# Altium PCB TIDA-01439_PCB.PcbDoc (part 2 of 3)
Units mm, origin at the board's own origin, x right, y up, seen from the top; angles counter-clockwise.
Board outline 105.8 x 40.5 mm, 4 copper layers (Layer 1 - Top Layer, Layer 2 - GND, Layer 3 - POWER, Layer 4 - Bottom Layer), stack 1.56 mm thick; 145 components, 123 nets, 523 pads, 227 vias.
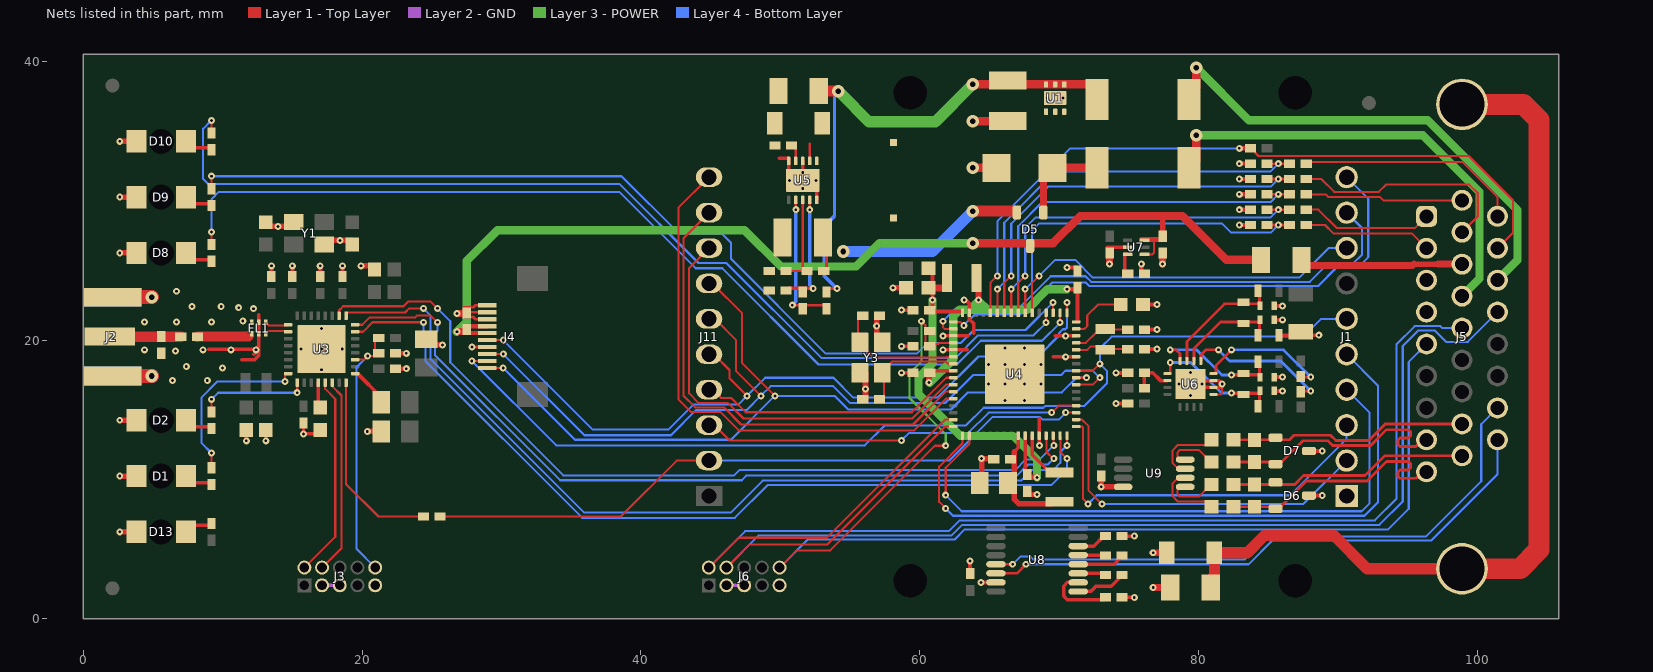
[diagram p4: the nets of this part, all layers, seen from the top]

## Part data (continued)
R10: "RES, 91.0 k, 0.1%, 0.1 W, 0603", Manufacturer="Susumu Co Ltd", Power_W=0.1, Supplier Part Number 1=RG16P91.0KBCT-ND, TempCo="25 ppm/C", Value1=0.1%, Value2=0.1W, Value_Code=91k0, ValueDisplayed=91.0k
R11: "RES, 10.0 k, 1%, 0.063 W, 0402", Manufacturer=Vishay-Dale, Power_W=0.063, Supplier Part Number 1=541-10.0KLCT-ND, TempCo="100 ppm/C", Tolerance_%=1, Value1=1%, Value2=0.063W, Value_Code=10k0, ValueDisplayed=10.0k
R13 R16 R21 R23 R25: "RES, 18.0 k, 1%, 0.063 W, AEC-Q200 Grade 0, 0402", Manufacturer=Vishay-Dale, Power_W=0.063, Supplier Part Number 1=541-18.0KLCT-ND, TempCo="100 ppm/C", Tolerance_%=1, Value1=1%, Value2=0.063W, Value_Code=18k0, ValueDisplayed=18.0k
R14 R19 R22 R24 R26: "RES, 33 k, 5%, 0.063 W, 0402", Manufacturer=Vishay-Dale, Power_W=0.063, Supplier Part Number 1=541-33KJCT-ND, TempCo="200 ppm/C", Tolerance_%=5, Value1=5%, Value2=0.063W, Value_Code=33k0, ValueDisplayed=33k
R15: "RES, 2.00 M, 1%, 0.063 W, 0402", Manufacturer=Vishay-Dale, Power_W=0.063, Supplier Part Number 1=541-2.00MLCT-ND, TempCo="100 ppm/C", Tolerance_%=1, Value1=1%, Value2=0.063W, Value_Code=2M00, ValueDisplayed=2.00M
R17: "RES, 130 k, 5%, 0.063 W, 0402", Manufacturer=Vishay-Dale, Power_W=0.063, Supplier Part Number 1=541-130KJCT-ND, TempCo="200 ppm/C", Tolerance_%=5, Value1=5%, Value2=0.063W, Value_Code=130k
R18: "RES, 110 k, 1%, 0.063 W, 0402", Manufacturer=Vishay-Dale, Power_W=0.063, Supplier Part Number 1=541-110KLCT-ND, TempCo="100 ppm/C", Tolerance_%=1, Value1=1%, Value2=0.063W, Value_Code=110k
R20: "RES, 24.9 k, 1%, 0.063 W, 0402", Manufacturer=Vishay-Dale, Power_W=0.063, Supplier Part Number 1=541-24.9KLCT-ND, TempCo="100 ppm/C", Tolerance_%=1, Value1=1%, Value2=0.063W, Value_Code=24k9, ValueDisplayed=24.9k
R27 R29 R30 R31: "RES, 4.12k ohm, 0.1%, 0.1W, 0603", Manufacturer="Susumu Co Ltd", Power_W=0.1, Supplier Part Number 1=RG16P4.12KBCT-ND, TempCo="25 ppm/C", Value1=0.1%, Value2=0.1W, Value_Code=4k12
R28: "RES, 3.24k ohm, 0.1%, 0.333W, 1206", Manufacturer="TT Electronics/IRC", Power_W=0.333, Supplier Part Number 1=66-PFC12L3.24K-B, TempCo="10 ppm/C", Tolerance_%=0.1, Value1=0.1%, Value2=0.333W, Value_Code=3k24
R32: "RES, 383 k, 1%, 0.063 W, 0402", Manufacturer=Vishay-Dale, Power_W=0.063, Supplier Part Number 1=541-383KLCT-ND, TempCo="100 ppm/C", Tolerance_%=1, Value1=1%, Value2=0.063W, Value_Code=383k
R34 R35 R36 R37: "RES, 10, 5%, 0.25 W, 0603", Manufacturer=Vishay-Dale, Power_W=0.25, Supplier Part Number 1=541-10SACT-ND, TempCo="200 ppm/C", Tolerance_%=5, Value1=5%, Value2=0.25W, Value_Code=10R0, ValueDisplayed=10
R41 R42: "RES, 120, 5%, 0.1 W, 0603", Manufacturer=Vishay-Dale, Power_W=0.1, Supplier Part Number 1=541-120GCT-ND, TempCo="200 ppm/C", Tolerance_%=5, Value1=5%, Value2=0.1W, Value_Code=120R, ValueDisplayed=120
R43 R44: "RES, 100, 5%, 0.25 W, 1206", Manufacturer=Vishay-Dale, Power_W=0.25, Supplier Part Number 1=541-100ECT-ND, TempCo="200 ppm/C", Tolerance_%=5, Value1=5%, Value2=0.25W, Value_Code=100R, ValueDisplayed=100
U1: "33V Precision Surge Protection Clamp, DRV0006A (WSON-6)", Alternate Manufacturer="Texas Instruments", Alternate PartNumber=TVS3300DRVT
U3: "Ultra low-power ARM Cortex M3 2.4 GHz Radio MCU, Multi-Protocol, RSHB032E", Alternate Manufacturer="Texas Instruments", Alternate PartNumber=CC2650F128RHBT
U4: "Low-Power and High Performance 32-Bit ARM Cortex M4F With 256KB Flash and 64KB RAM, RGC0064B (VQFN-64)", Alternate Manufacturer="Texas Instruments", Alternate PartNumber=MSP432P401RIRGCT
U5: "3V-65V, 150mA Synchronous Buck Converter With Ultra-Low IQ, DRC0010J (VSON-10)", Alternate Manufacturer="Texas Instruments", Alternate PartNumber=LM5165DRCT
U6: "24-Bit, 2kSPS, 4-Ch, Low-Power, Delta-Sigma ADC with PGA  and Voltage Reference, RVA0016A (VQFN-16)", Alternate Manufacturer="Texas Instruments", Alternate PartNumber=ADS1220IRVAT
U7: "Single Output High PSRR LDO, 150 mA, Fixed 3.3 V Output, 2.5 to 6.5 V Input, with Low IQ, 6-pin WSON (DSE), -40 to 125 degC, Green (RoHS & no Sb/Br)", Alternate Manufacturer="Texas Instruments", Alternate PartNumber=Equivalent, Supplier Part Number 1=296-22054-2-ND
U8: "3-V to 5.5-V Multichannel RS-232 Line Driver / Receiver with ±15-kV IEC ESD Protection, -40 to 85 degC, 16-Pin TSSOP (PW), Green (RoHS & no Sb/Br)", Alternate Manufacturer="Texas Instruments", Alternate PartNumber=Equivalent, Drivers Per Package=2, Supplier Part Number 1=296-19436-2-ND, Supply Voltage(s)(V)="3.3 or 5.0"
U9: "3.3-V Full-Duplex RS-485 Transceivers With 12-kV IEC ESD, DGK0008A (VSSOP-8)", Alternate Manufacturer="Texas Instruments", Alternate PartNumber=SN65HVD71DGK
Y1: "Crystal, 24 MHz, 9 pF, SMD", Frequency="24 MHz", Frequency Stability=±20ppm, Manufacturer=Epson, Supplier Part Number 1=SER3634CT-ND
Y2 Y4: "Crystal, 32.768kHz, 12.5pF, SMD", Frequency=32.768KHZ, Frequency Stability=±20ppm, Manufacturer=Epson, Supplier Part Number 1=SER3672CT-ND
Y3: "Crystal, 48MHz, 12pF, SMD", Frequency=48MHz, Frequency Stability=±30ppm, Manufacturer=Epson, Supplier Part Number 1="FA-238 48.0000MB-W0-ND"
ZZ1: library part AssemblyNoteLabel, Alternate Manufacturer=-
ZZ2 ZZ3 ZZ4: library part AssemblyNote, Alternate Manufacturer=-

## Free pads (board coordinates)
  round 0.1 hole 2.4 unplated paste-1 mask+0.1: ""(59.3,2.75) ""(59.3,37.75) ""(86.9,2.75) ""(86.9,37.75)

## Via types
v1: diameter 0.5, hole 0.2, Layer 1 - Top Layer to Layer 4 - Bottom Layer, 215 vias
v2: diameter 0.9, hole 0.4, Layer 1 - Top Layer to Layer 4 - Bottom Layer, 12 vias

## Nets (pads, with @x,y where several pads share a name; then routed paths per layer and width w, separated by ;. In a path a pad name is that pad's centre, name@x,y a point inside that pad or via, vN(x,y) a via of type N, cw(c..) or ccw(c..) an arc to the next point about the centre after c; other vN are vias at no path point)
5V: C6.1 C28.1 D5.3 J4.6 J4.7 R43.1 U7.4 U7.6 | length 81.5
  Layer 1 - Top Layer w0.15: U7.4@76.1,26.15 76.675,26.15 76.775,26.25 76.775,27.075
  Layer 1 - Top Layer w0.25: 75.875,27.275 77.575,27.275 77.575,27.15 U7.6@76.1,27.15
  Layer 1 - Top Layer w0.3: J4.6@28.974,20.496 27.5,20.496 C6.1@27.5,20.75 27.5,20.996 J4.7@28.974,20.996
  Layer 1 - Top Layer w0.4: C28.1@77.4,27.45 77.4,28.8
  Layer 1 - Top Layer w0.5: v1(26.8,20.6) C6.1@27.397,20.6
  Layer 1 - Top Layer w0.6: D5.3@67.9,26.9 67.85,26.95 v2(63.8,26.95) 69.55,26.95 71.5,28.9 78.825,28.9 81.975,25.75 R43.1@84.45,25.75
  Layer 3 - POWER w0.6: v1(26.8,20.6) 27.5,21.3 27.5,25.675 29.7,27.875 47.425,27.875 50.025,25.275 55.425,25.275 57.1,26.95 v2(63.8,26.95)
5V_IN: F1.2 J5.13 | length 31.8
  Layer 1 - Top Layer w0.6: F1.2@79.825,32.875 v2(79.825,34.675)
  Layer 3 - POWER w0.6: v2(79.825,34.675) 96.075,34.675 100.125,30.625 100.125,24.405 J5.13@98.87,23.15
5V_OUT: J5.12 R43.2 | length 12
  Layer 1 - Top Layer w0.4: 95.415,25.44 97.16,25.44
  Layer 1 - Top Layer w0.5: R43.2@87.35,25.333 95.308,25.333 95.415,25.44 ; 97.16,25.44 J5.12@98.87,25.44
  Layer 1 - Top Layer w0.6: R43.2@87.35,25.333 R43.2@87.35,25.75
24V_IN: F2.2 J5.21 | length 34.4
  Layer 1 - Top Layer w0.6: F2.2@79.825,38.05 v2(79.825,39.525)
  Layer 3 - POWER w0.6: v2(79.825,39.525) 83.6,35.75 96.425,35.75 102.85,29.325 102.85,25.735 J5.21@101.41,24.295
AIN0: C44.2 C45.2 R31.2 U6.9 | length 9.4
  Layer 1 - Top Layer w0.2: U6.9@77.75,17.6 77.95,17.6 v1(77.95,18.4)
  Layer 1 - Top Layer w0.25: v1(82.35,16.2) 84.35,16.2 84.35,15.25 R31.2@84.238,15.25
  Layer 4 - Bottom Layer w0.2: v1(77.95,18.4) 79.418,18.4 81.618,16.2 v1(82.35,16.2)
AIN1: C43.1 C44.1 R30.2 U6.8 | length 9.5
  Layer 1 - Top Layer w0.2: v1(77.95,19.3) 78.375,19.3 78.65,19.025 U6.8@78.65,18.5
  Layer 1 - Top Layer w0.25: v1(82.35,17.5) 84.35,17.5 84.35,18.45 R30.2@84.238,18.45
  Layer 4 - Bottom Layer w0.2: v1(77.95,19.3) 79.85,19.3 81.65,17.5 v1(82.35,17.5)
AIN2: D4.2 U6.5 | length 10.5
  Layer 1 - Top Layer w0.2: U6.5@80.15,18.5 80.15,18.95 80.5,19.3 v1(81.4,19.3) ; D4.2@87.3,16.3 87.3,16.35 v1(88.025,16.35)
  Layer 4 - Bottom Layer w0.2: v1(81.4,19.3) 82.2,18.5 85.875,18.5 v1(88.025,16.35)
AIN3: D3.2 U6.4 | length 9.6
  Layer 1 - Top Layer w0.2: U6.4@81.05,17.6 81.225,17.6 81.225,18.175 v1(82.35,19.3) ; D3.2@87.3,17.4 87.3,17.35 v1(88.025,17.35)
  Layer 4 - Bottom Layer w0.2: v1(82.35,19.3) 86.075,19.3 v1(88.025,17.35)
CC2650_CLK: U3.26 U4.14 | length 60.4
  Layer 1 - Top Layer w0.15: U3.26@18.35,21.75 18.35,22.125 18.65,22.425 22.975,22.425 23.325,22.775 24.9,22.775 v1(25.4,22.275) ; v1@69.575,12.45 U4.14@69.575,13.15
  Layer 4 - Bottom Layer w0.15: v1(25.4,22.275) 26.325,21.35 26.325,18.4 34.425,10.3 46.675,10.3 47.05,10.675 66.825,10.675 67.6,11.45 68.6,11.45 v1(69.6,12.45)
CC2650_NCS: U3.24 U4.13 | length 59.4
  Layer 1 - Top Layer w0.15: U3.24@19.5,21.1 20.025,21.1 20.55,21.625 23.825,21.625 23.975,21.775 24.9,21.775 v1(25.4,21.275) ; U4.13@69.025,13.175 U4.13@69.05,13.15 69.075,13.125 69.075,11.975 v1@69.55,11.5
  Layer 4 - Bottom Layer w0.15: v1(25.4,21.275) 25.4,20.65 25.225,20.475 25.225,18.925 34.2,9.95 47.225,9.95 47.55,10.275 66.95,10.275 67.75,11.075 69.175,11.075 v1(69.6,11.5)
CC2650_SIMO: U3.25 U4.16 | length 63.1
  Layer 1 - Top Layer w0.15: U3.25@18.85,21.75 18.85,21.975 23.075,21.975 23.375,22.275 v1(24.4,22.275) ; v1(70.55,12.45) U4.16@70.55,13.15
  Layer 4 - Bottom Layer w0.15: v1(24.4,22.275) 24.9,21.775 24.9,18.65 35.925,7.625 46.425,7.625 48.725,9.925 67.25,9.925 68,10.675 69.55,10.675 70.075,11.2 70.075,11.975 v1(70.55,12.45)
CC2650_SOMI: U3.23 U4.15 | length 62.8
  Layer 1 - Top Layer w0.15: U3.23@19.5,20.6 20.075,20.6 20.75,21.275 v1(24.4,21.275) ; U4.15@70.05,13.15 70.075,13.125 70.075,11.975 v1(70.55,11.5)
  Layer 4 - Bottom Layer w0.15: v1(24.4,21.275) 24.4,20.7 24.55,20.55 24.55,18.475 35.775,7.25 46.725,7.25 49.075,9.6 69.425,9.6 70.55,10.725 v1(70.55,11.5)
DCDC_SW: L2.1 U3.17 | length 2.6
  Layer 1 - Top Layer w0.25: U3.17@19.5,17.6 19.675,17.6 21.384,15.891 L2.1@21.384,15.85
GND: C1.2 C2.2 C3.2 C4.2 C5.2 C6.2 C7.2 C8.2 C9.2 C10.2 C11.2 C13.2 C14.2 C15.1 C16.2 C17.2 C18.2 C19.2 C20.2 C21.2 C22.2 C23.2 C24.2 C25.2 C26.2 C27.2 C28.2 C29.1 C30.2 C31.2 C32.2 C33.2 C34.2 C35.1 C36.2 C37.1 C38.2 C40.1 C41.2 C42.2 C43.2 C45.1 C48.2 C49.2 C50.2 C51.2 C52.2 C53.1 D1.2 D2.2 D6.3 D7.3 D8.2 D9.2 D10.2 D11.2 D13.2 FL1.2 FL1.5 FL1.6 J1.1 J2.2 J2.3 J2.4 J2.5 J3.3 J3.5 J3.9 J4.4 J4.8 J4.9 J4.10 J5.3 J5.4 J6.3 J6.5 J6.9 R10.1 R14.1 R18.1 R19.1 R20.1 R22.1 R24.1 R26.1 R28.1 R29.1 R44.1 U1.1 U1.2 U1.3 U1.7@69.7,37.35 U3.33 U4.12 U4.27 U4.30 U4.47 U4.51 U4.53 U4.65@66.8,17.55 U5.3 U5.5 U5.10 U5.11 U6.1 U6.2 U6.3 U6.17 U7.2 U8.15 U9.4 Y1.2 Y1.4 Y3.2 Y3.4 | length 119.9
  Layer 1 - Top Layer w0.15: U6.1@81.05,16.1 81.55,16.1 81.675,16.225 v1(81.675,16.85)
  Layer 1 - Top Layer w0.2: C6.2@27.3,22.35 28,22.35 28.146,22.497 J4.10@28.974,22.497 ; C6.2@27.35,21.65 27.975,21.65 28.129,21.497 J4.8@28.974,21.497 ; C6.2@27.428,21.996 27.5,21.996 J4.9@28.974,21.996 ; v1(27.879,19.496) J4.4@28.974,19.496
  Layer 1 - Top Layer w0.25: 8.996,19.325 12.354,19.325 12.575,19.546 ; 11.375,18.575 12.275,18.575 12.575,18.875 v1@12.575,19.3 ; FL1.6@12.079,21.2 FL1.6@12.079,21.278 ; 12.25,18.975 v1@12.575,19.3 ; 12.575,19.55 12.575,19.546 ; 12.579,21.8 FL1.5@12.579,21.278 FL1.2@12.579,20.453 12.579,19.55 12.575,19.546 ; C3.2@15.8,14.1 v1(15.8,13.275) 17.2,13.275 C13.2@17.2,13.6 ; C18.2@19.1,26.85 19.1,27.15 C18.2@19.1,27.225 ; 49.9,33.025 50.6,33.025 U5.5@50.6,32.85 U5.11@50.6,31.8 ; U5.11@51.6,31.525 v1(51.6,32.025) U5.3@51.6,32.85 ; U5.10@52.6,30.05 U5.11@52.6,30.975 ; v1(58.675,17.65) C22.2@59.5,17.65 ; v1(58.675,19.55) C34.2@59.5,19.55 ; v1(58.675,22.15) C25.2@59.5,22.15 ; v1(61.65,19.3) 62.4,19.3 63.4,19.3 ; v1(61.65,20.3) U4.51@62.401,20.3 ; U4.51@62.4,20.301 63.449,20.301 ; v1(63.175,22.875) 63.3,22.875 63.55,22.625 U4.47@63.55,21.95 63.55,21.5 63.875,21.175 63.875,20.5 ; C24.2@67.7,9.15 C24.2@67.7,9.425 ; 68.55,14.375 U4.12@68.55,13.15 68.55,12.475 v1(68.575,12.45) ; 69.575,18.8 v1(70.45,18.8) ; 69.7,20.3 v1(70.45,20.3) ; v1(70.45,18.8) U4.27@71.2,18.8 ; v1(70.45,20.3) U4.30@71.2,20.301 ; 73.425,26.65 U7.2@74.9,26.65 ; C48.2@74.5,1.55 v1(75.375,1.55) ; C49.2@74.5,5.95 v1(75.375,5.95) ; U6.17@80.325,16.6 U6.2@81.05,16.6 81.675,16.6 v1(81.675,16.85) 81.425,17.1 U6.3@81.05,17.1 U6.17@80.375,17.1 ; R29.1@85.877,20.235 R29.1@85.762,20.35 v1(88.6,20.35) ; v1@12.575,19.3 12.575,19.546
  Layer 1 - Top Layer w0.3: v1(11.7,12.775) C15.1@11.7,13.55 ; v1(13.1,12.775) C16.2@13.1,13.55 ; C10.2@13.5,24.55 v1(13.5,25.325) ; C9.2@15,24.55 v1(15,25.325) ; C8.2@17,24.55 v1(17,25.325) ; C2.2@18.6,24.55 v1(18.6,25.325) ; C5.2@22.4,17.95 v1(23.175,17.95) ; C14.2@22.4,19.05 v1(23.175,19.05) ; C50.2@63.6,3.25 v1(63.6,4.15) ; v1(64.375,2.625) U8.15@65.45,2.625 U8.15@65.65,2.625 ; v1(70.55,25.2) 71.3,25.2 C21.2@71.3,24.95 ; v1(74.05,15.45) C42.2@74.9,15.45 ; v1(74.05,17.65) C41.2@74.9,17.65 ; v1(75.875,25.45) 75.875,24.975 C30.2@76.1,24.75 ; R10.1@76,22.55 v1(77,22.55) ; C35.1@76.1,19.35 v1(77,19.35) ; C37.1@76.1,20.75 v1(77,20.75) ; v1(82.9,28.25) R26.1@83.7,28.25 ; v1(82.9,29.35) R24.1@83.7,29.35 ; v1(82.9,30.45) R22.1@83.7,30.45 ; v1(82.9,31.55) R19.1@83.7,31.55 ; v1(82.9,32.65) R14.1@83.7,32.65 ; C45.1@85.408,16.35 v1(86,16.35) ; C43.2@85.408,17.35 v1(86,17.35) ; C40.1@85.408,21.45 v1(86,21.45) ; C38.2@85.408,22.45 v1(86,22.45) ; D6.3@87.9,8.85 v1(88.85,8.85) ; D7.3@87.9,12.05 v1(88.85,12.05)
  Layer 1 - Top Layer w0.35: C24.2@67.7,8.925 v1(68.4,8.925)
  Layer 1 - Top Layer w0.4: v1(2.625,6.25) D13.2@3.82,6.25 ; v1(2.625,10.25) D1.2@3.82,10.25 ; v1(2.625,14.25) D2.2@3.82,14.25 ; v1(2.625,26.25) D8.2@3.82,26.25 ; v1(2.625,30.25) D9.2@3.82,30.25 ; v1(2.625,34.25) D10.2@3.82,34.25 ; C17.2@13.1,28.45 13.1,28.15 v1(13.975,28.15) 15.1,28.15 Y1.2@15.1,28.45 ; Y1.4@17.3,26.85 17.3,27.15 v1(18.425,27.15) 19.1,27.15 C18.2@19.2,27.15 ; C18.2@19.2,26.85 C18.2@19.2,27.15 ; C18.2@19.3,26.85 19.3,27.15 C18.2@19.2,27.15 ; v1(19.925,25.325) 20.9,25.325 C1.2@20.9,25.05 ; v1(20.375,13.45) C7.2@21.384,13.45 ; C4.2@24.6,20.266 25.216,19.65 v1(25.775,19.65) ; Y3.4@55.3,17.65 Y3.4@55.7,17.65 56.1,17.65 v1(56.1,16.5) C32.2@56.1,15.75 ; C29.1@56.9,21.75 v1(56.9,21) 56.9,19.85 Y3.2@57.3,19.85 ; v1(58.075,23.75) C23.2@59,23.75 ; C19.2@64.284,9.75 64.425,9.891 v1(64.425,11.5) 65.25,11.5 C20.2@65.3,11.45 ; C52.2@73,10.25 v1(73,9.475) U9.4@74.575,9.475
  Layer 1 - Top Layer w0.5: v1(26.8,21.9) 27.404,21.9 27.5,21.996 C6.2@27.5,21.95 ; v1(73.6,25.45) C51.2@73.6,26.25 ; v1(76.725,2.25) R44.1@77.95,2.25 ; v1(76.725,4.75) C53.1@77.7,4.75 ; v1(77.4,25.45) C28.2@77.4,26.25
  Layer 1 - Top Layer w0.6: v2(63.8,32.35) D11.2@65.5,32.35 ; v2(63.8,35.7) C33.2@66.3,35.7
  Layer 1 - Top Layer w1: J2.3@2.1,17.425 v2(4.925,17.425) ; J2.2@2.1,23.075 v2(4.925,23.075)
  Layer 2 - GND w0.25: J3.3@17.13,2.415 J3.5@18.4,2.415 ; J6.3@46.13,2.415 J6.5@47.4,2.415
  Layer 4 - Bottom Layer w0.9: J2.4@2.1,23.075 v2(4.925,23.075)
  Layer 4 - Bottom Layer w1: J2.5@2.1,17.425 v2(4.925,17.425)
  other v1: 66.105,15.675 67.495,15.675 79.4,16.03 64.925,16.855 66.105,16.855 67.495,16.855 68.675,16.855 78.58,16.85 80.22,16.85 6.4,17.1 8.9,17.1 79.4,17.67 17.1,17.875 10,18 7.4,18.1 64.925,18.245 66.105,18.245 67.495,18.245 68.675,18.245 6.625,19.225 4.4,19.3 8.6,19.3 10.6,19.3 12.4,19.3 15.625,19.35 17.1,19.35 18.575,19.35 66.105,19.425 67.495,19.425 17.1,20.825 4.4,21.3 6.7,21.3 9.2,21.3 11.45,21.375 12.225,22.25 11.15,22.325 7.8,22.4 9.9,22.4 6.7,23.5 51.6,30.875 50.65,31.45 52.55,31.45 69.15,37.35 70.25,37.35
HFXIN: C32.1 U4.55 Y3.1 | length 7.5
  Layer 1 - Top Layer w0.15: C32.1@57.2,15.75 57.425,15.975 57.425,17.875 58,18.45 61.85,18.45 62,18.3 U4.55@62.4,18.3
HFXOUT: C29.2 U4.54 Y3.3 | length 9.4
  Layer 1 - Top Layer w0.15: C29.2@55.8,21.825 55.575,21.6 55.575,19.85 56.675,18.75 61.875,18.75 61.925,18.8 U4.54@62.4,18.8
IN0_DIV: R25.1 R26.2 U4.39 | length 26.1
  Layer 1 - Top Layer w0.15: U4.39@67.55,21.95 v1(67.55,23.65)
  Layer 1 - Top Layer w0.2: R26.2@84.9,28.25 v1(85.7,28.25) R25.1@86.5,28.25
  Layer 4 - Bottom Layer w0.15: v1(67.55,23.65) 68.05,24.15 68.05,27.875 68.525,28.35 81.675,28.35 82.325,27.7 85.15,27.7 v1(85.7,28.25)
IN1_DIV: R23.1 R24.2 U4.40 | length 26.6
  Layer 1 - Top Layer w0.15: U4.40@67.05,21.95 67.05,24.1 v1(67.55,24.6)
  Layer 1 - Top Layer w0.2: R24.2@84.9,29.35 v1(85.7,29.35) R23.1@86.5,29.35
  Layer 4 - Bottom Layer w0.15: v1(67.55,24.6) 67.55,28.05 68.3,28.8 85.15,28.8 v1(85.7,29.35)
IN2_DIV: R21.1 R22.2 U4.41 | length 27.6
  Layer 1 - Top Layer w0.15: U4.41@66.55,21.95 v1(66.55,23.65)
  Layer 1 - Top Layer w0.2: R22.2@84.9,30.45 v1(85.7,30.45) R21.1@86.5,30.45
  Layer 4 - Bottom Layer w0.15: v1(66.55,23.65) 67.05,24.15 67.05,28.175 68.775,29.9 85.15,29.9 v1(85.7,30.45)
IN3_DIV: R16.1 R19.2 U4.42 | length 28.7
  Layer 1 - Top Layer w0.15: U4.42@66.05,21.95 66.05,24.1 v1(66.55,24.6)
  Layer 1 - Top Layer w0.2: R19.2@84.9,31.55 v1(85.7,31.55) R16.1@86.5,31.55
  Layer 4 - Bottom Layer w0.15: v1(66.55,24.6) 66.55,28.35 69.2,31 85.15,31 v1(85.7,31.55)
IN4_DIV: R13.1 R14.2 U4.43 | length 29.7
  Layer 1 - Top Layer w0.15: U4.43@65.55,21.95 v1(65.55,23.65)
  Layer 1 - Top Layer w0.2: R14.2@84.9,32.65 v1(85.7,32.65) R13.1@86.5,32.65
  Layer 4 - Bottom Layer w0.15: v1(65.55,23.65) 66.05,24.15 66.05,28.425 69.725,32.1 85.15,32.1 v1(85.7,32.65)
IN5_DIV: J5.20 R11.1 U4.44 | length 51.4
  Layer 1 - Top Layer w0.15: U4.44@65.05,21.95 65.05,24.1 v1(65.55,24.6) ; R11.1@83.7,33.75 83.725,33.75 84.275,33.2 99.35,33.2 102.525,30.025 102.525,27.7 J5.20@101.41,26.585
  Layer 1 - Top Layer w0.3: v1(82.9,33.75) R11.1@83.7,33.75
  Layer 4 - Bottom Layer w0.15: v1(65.55,24.6) 65.55,28.525 70.775,33.75 v1(82.9,33.75)
IN_0: J5.2 R25.2 | length 9.3
  Layer 1 - Top Layer w0.15: R25.2@87.7,28.25 89.05,28.25 89.65,27.65 95.265,27.65 J5.2@96.33,26.585
IN_1: J5.1 R23.2 | length 9.5
  Layer 1 - Top Layer w0.15: R23.2@87.7,29.35 88.575,29.35 89.875,28.05 95.505,28.05 J5.1@96.33,28.875
IN_2: J5.10 R21.2 | length 11.3
  Layer 1 - Top Layer w0.15: R21.2@87.7,30.45 89.1,30.45 89.3,30.25 93,30.25 93.23,30.02 J5.10@98.87,30.02
IN_3: J5.11 R16.2 | length 16.4
  Layer 1 - Top Layer w0.15: R16.2@87.7,31.55 88.775,31.55 89.7,30.625 92.9,30.625 93.425,31.15 99.4,31.15 100,30.55 100,28.86 J5.11@98.87,27.73
IN_4: J5.19 R13.2 | length 16.2
  Layer 1 - Top Layer w0.15: R13.2@87.7,32.65 87.825,32.775 98.9,32.775 101.41,30.265 J5.19@101.41,28.875
JTAG_TCK: J3.4 U3.14 | length 14.1
  Layer 1 - Top Layer w0.15: J3.4@17.13,3.685 18.525,5.08 18.525,16.025 17.85,16.7 U3.14@17.85,16.95
JTAG_TMS: J3.2 U3.13 | length 14.5
  Layer 1 - Top Layer w0.15: J3.2@15.86,3.685 18.075,5.9 18.075,15.775 17.35,16.5 U3.13@17.35,16.95
LCD_CLK: J4.1 J11.7 U4.24 | length 58.7
  Layer 1 - Top Layer w0.15: J4.1@28.974,17.996 v1(30.121,17.996) ; J11.7@44.88,24.06 45.115,24.06 47.25,21.925 47.25,18.35 v1(49.6,16) ; U4.24@71.2,17.3 v1(71.95,17.3)
  Layer 4 - Bottom Layer w0.15: v1(30.121,17.996) 35.268,12.85 46.45,12.85 v1(49.6,16) 53.875,16 54.85,15.025 62.225,15.025 63.45,16.25 70.175,16.25 71.225,17.3 v1(71.95,17.3)
LCD_CS: J4.3 J11.6 U4.23 | length 58.7
  Layer 1 - Top Layer w0.15: J4.3@28.974,18.996 v1(30.125,18.996) ; J11.6@44.88,21.52 45.305,21.52 46.825,20 46.825,17.775 v1(48.6,16) ; U4.23@71.2,16.8 72.4,16.8 v1(72.9,17.3)
  Layer 4 - Bottom Layer w0.15: v1(30.125,18.996) 35.946,13.175 42.15,13.175 43.975,15 47.6,15 v1(48.6,16) 49.3,16.7 53.775,16.7 55,15.475 61.8,15.475 63.825,17.5 70.125,17.5 70.425,17.8 72.4,17.8 v1(72.9,17.3)
LCD_DISP: J4.5 J11.5 U4.33 | length 55.4
  Layer 1 - Top Layer w0.15: J4.5@28.974,19.997 28.978,20 v1(30.125,20) ; J11.5@44.88,18.98 45.22,18.98 46.35,17.85 46.35,17.25 v1(47.6,16) ; U4.33@70.55,21.95 v1(70.55,22.7)
  Layer 4 - Bottom Layer w0.15: v1(30.125,20) 36.55,13.575 41.95,13.575 43.75,15.375 46.975,15.375 v1(47.6,16) 48.9,17.3 53.8,17.3 55.225,15.875 61.25,15.875 64.2,18.825 68.475,18.825 69.975,20.325 69.975,20.497 70.253,20.775 70.425,20.775 70.55,20.9 v1(70.55,22.7)
LCD_SIMO: J1.6 J4.2 U4.25 | length 74.2
  Layer 1 - Top Layer w0.15: v1(27.871,18.496) J4.2@28.974,18.496 ; U4.25@71.2,17.8 72.4,17.8 v1(72.9,18.3)
  Layer 4 - Bottom Layer w0.15: v1(27.871,18.496) 33.918,12.45 56.05,12.45 57.475,13.875 63.3,13.875 64.575,15.15 68.85,15.15 68.975,15.275 71.775,15.275 73.425,16.925 73.425,17.775 v1(72.9,18.3) 72.9,19.4 73.75,20.25 87.5,20.25 88.77,21.52 J1.6@90.6,21.52
LED1: R33.2 U4.34 | length 71.4
  Layer 1 - Top Layer w0.15: R33.2@9.2,26.85 v1(9.2,27.75) ; v1(70.05,21.25) U4.34@70.05,21.95
  Layer 4 - Bottom Layer w0.15: v1(9.2,27.75) 9.2,30.1 9.725,30.625 38.45,30.625 43.925,25.15 45.825,25.15 52.725,18.25 62.65,18.25 64.35,19.95 68.75,19.95 v1(70.05,21.25)
LED2: R39.1 U4.35 | length 69.3
  Layer 1 - Top Layer w0.15: R39.1@9.2,30.85 v1(9.2,31.75) ; U4.35@69.55,21.95 v1(69.55,22.7)
  Layer 4 - Bottom Layer w0.15: v1@9.3,31.75 38.6,31.75 42.7,27.65 45.775,27.65 46.45,26.975 46.45,25.825 53.225,19.05 59.8,19.05 60.55,19.8 62.95,19.8 63.875,20.725 67.575,20.725 v1(69.55,22.7)
LED3: R38.1 U4.36 | length 72.9
  Layer 1 - Top Layer w0.15: R38.1@9.2,34.85 v1(9.2,35.75) ; v1(69.05,21.25) U4.36@69.05,21.95
  Layer 4 - Bottom Layer w0.15: v1(9.2,35.75) 8.6,35.15 8.6,31.55 8.95,31.2 38.45,31.2 44.125,25.525 46.125,25.525 52.95,18.7 62.525,18.7 64.15,20.325 68.125,20.325 v1(69.05,21.25)
LED_GREEN: R4.2 U3.8 | length 12.6
  Layer 1 - Top Layer w0.15: R4.2@9.2,10.85 v1(9.2,11.9) ; v1(14.475,17.025) 14.475,17.6 U3.8@14.7,17.6
  Layer 4 - Bottom Layer w0.15: v1(9.2,11.9) 8.475,12.625 8.475,15.875 9.625,17.025 v1(14.475,17.025)
LED_RED: R5.1 U3.9 | length 8
  Layer 1 - Top Layer w0.15: R5.1@9.2,14.85 v1(9.2,15.75) ; v1(15.35,16.225) U3.9@15.35,16.95
  Layer 4 - Bottom Layer w0.15: v1(9.2,15.75) 9.675,16.225 v1(15.35,16.225)
LFXIN: C35.2 U4.28 Y4.2 | length 3.9
  Layer 1 - Top Layer w0.15: U4.28@71.2,19.3 72,19.3 72.25,19.55 73.05,19.55 Y4.2@73.3,19.3 73.35,19.35 C35.2@74.9,19.35
LFXOUT: C37.2 U4.29 Y4.1 | length 4.1
  Layer 1 - Top Layer w0.15: U4.29@71.2,19.801 71.901,19.801 72.625,20.525 73.025,20.525 Y4.1@73.3,20.8 73.35,20.75 C37.2@74.9,20.75
MSP_JTAG_TCK: J5.22 J6.4 U4.64 | length 90.5
  Layer 1 - Top Layer w0.15: J6.4@46.13,3.685 47.795,5.35 53.375,5.35 61.824,13.799 U4.64@62.4,13.799
  Layer 4 - Bottom Layer w0.15: J6.4@46.13,3.685 48.445,6 62.275,6 63.025,6.75 92.95,6.75 94.625,8.425 94.625,19.575 95.75,20.7 96.9,20.7 97.725,19.875 99.28,19.875 J5.22@101.41,22.005
MSP_JTAG_TMS: J5.14 J6.2 U4.63 | length 89.7
  Layer 1 - Top Layer w0.15: J6.2@44.86,3.685 47,5.825 53.325,5.825 61.799,14.299 U4.63@62.4,14.299
  Layer 4 - Bottom Layer w0.15: J6.2@44.86,3.685 47.475,6.3 62.075,6.3 62.85,7.075 92.625,7.075 94.175,8.625 94.175,19.7 95.475,21 97.325,21 97.465,20.86 J5.14@98.87,20.86
MSP_NRST: C34.1 J5.5 J6.10 R9.1 U4.52 | length 88.9
  Layer 1 - Top Layer w0.15: J6.10@49.94,3.685 51.18,4.925 53.575,4.925 61.075,12.425 v1(61.85,12.425) ; v1(60.1,21.35) 60.4,21.05 60.4,19.725 61.325,19.725 61.401,19.801 U4.52@62.4,19.801
  Layer 3 - POWER w0.15: v1(60.1,21.35) 60.1,18.45 59.25,17.6 59.25,15.85 61.85,13.25 v1(61.85,12.425)
  Layer 4 - Bottom Layer w0.15: J6.10@49.94,3.685 51.955,5.7 62.5,5.7 63.225,6.425 93.575,6.425 95.05,7.9 95.05,18.435 J5.5@96.33,19.715
MSP_VSW: L3.1 U4.11 | length 3.7
  Layer 1 - Top Layer w0.25: U4.11@68.05,13.15 68.05,11.775 L3.1@69.225,10.6 ; L3.1@69.225,10.4 L3.1@69.9,10.4
NetC11_1: C11.1 J2.1 R1.1 | length 5.1
  Layer 1 - Top Layer w0.762: J2.1@1.9,20.25 C11.1@5.6,20.25 R1.1@7,20.25
NetC13_1: C13.1 U3.12 | length 2.1
  Layer 1 - Top Layer w0.254: U3.12@16.85,16.95 16.85,15.2 C13.1@17.2,15.2
NetC19_1: C19.1 C20.1 L3.2 U4.9 | length 7.6
  Layer 1 - Top Layer w0.25: 66.75,11.975 67.05,12.275 U4.9@67.05,13.15
  Layer 1 - Top Layer w0.4: 66.75,11.975 66.75,8.6 67.1,8.25 69.45,8.25 L3.2@69.475,8.275
NetC21_1: C21.1 C22.1 L4.2 U4.32 U4.56 | length 26.1
  Layer 1 - Top Layer w0.25: C22.1@60.45,17.8 U4.56@62.4,17.8
  Layer 1 - Top Layer w0.3: v1(70.55,23.65) C21.1@71.3,23.65 ; U4.32@71.3,21.35 C21.1@71.3,23.65 ; C21.1@71.3,23.75 C21.1@71.3,23.65
  Layer 1 - Top Layer w0.4: v1(60.65,16.95) 60.65,17.675 C22.1@60.675,17.7 ; L4.2@64.05,24.45 L4.2@64.2,24.3 ; v1(64.2,22.875) L4.2@64.2,24.3 ; L4.2@64.2,25.25 L4.2@64.2,24.3
  Layer 3 - POWER w0.5: 63.5,22.175 v1(64.2,22.875) ; 64.2,22.15 64.2,22.175 v1(64.2,22.875) ; 65.35,22.175 64.9,22.175 v1(64.2,22.875)
  Layer 3 - POWER w0.6: v1@60.7,16.925 62.4,18.625 62.4,21.725 62.85,22.175 63.5,22.175 64.2,22.175 64.9,22.175 67.675,22.175 69.15,23.65 v1(70.55,23.65)
NetC23_1: C23.1 C24.1 C25.1 L4.1 L6.1 U4.10 U4.48 | length 29.6
  Layer 1 - Top Layer w0.25: C24.1@67.55,10.35 U4.10@67.55,13.35
  Layer 1 - Top Layer w0.3: L6.1@60.3,25.087 L6.1@60.662,25.087 ; C25.1@60.7,22.05 C25.1@60.9,22.05 ; L6.1@60.9,25.087 v1(60.9,22.875) C25.1@60.9,22.05 ; U4.48@63,22.05 C25.1@60.9,22.05
  Layer 1 - Top Layer w0.4: C24.1@67.675,10.15 v1(68.4,10.15)
  Layer 1 - Top Layer w0.5: C23.1@60.6,23.75 L4.1@61.925,23.75
  Layer 3 - POWER w0.6: v1(60.9,22.875) 60.9,18.325 59.9,17.325 59.9,16.125 62.9,13.125 66.7,13.125 68.4,11.425 v1(68.4,10.15)
NetC26_1: C26.1 C33.1 C36.1 F2.1 R15.2 U1.4 U1.5 U1.6 U5.2 | length 37.8
  Layer 1 - Top Layer w0.2: U5.2@52.1,32.85 52.1,34.05 ; R15.2@53.3,23.7 v1(54.05,23.7)
  Layer 1 - Top Layer w0.6: v2(63.8,38.35) 72.425,38.35 F2.1@72.625,38.15
  Layer 1 - Top Layer w0.8: C36.1@53.225,37.85 v2(54.15,37.85)
  Layer 3 - POWER w0.8: v2@54.325,37.675 56.35,35.65 61.1,35.65 v2(63.8,38.35)
  Layer 4 - Bottom Layer w0.25: v2@53.875,37.625 53.875,28.9 53.15,28.175 53.15,24.65 53.125,24.625 v1(54.05,23.7)
NetC27_1: C27.1 D5.2 L7.2 R32.2 | length 16.8
  Layer 1 - Top Layer w0.2: C27.1@52.8,26.9 52.8,28.55 C27.1@53.1,28.55 ; R32.2@53.1,24.95 53.3,24.95 C27.1@53.3,26.1
  Layer 1 - Top Layer w0.8: v2(63.8,29.25) D5.2@66.825,29.25
  Layer 4 - Bottom Layer w0.8: v2(54.5,26.35) 60.9,26.35 v2(63.8,29.25)
NetC30_1: C30.1 U7.3 | length 1.9
  Layer 1 - Top Layer w0.254: C30.1@74.9,24.75 74.675,24.75 74.675,26.15 U7.3@74.9,26.15
NetC31_1: C31.1 U5.4 | length 1.1
  Layer 1 - Top Layer w0.2: U5.4@51.1,32.85 C31.1@51.1,33.925
NetC41_1: C41.1 L5.2 U6.10 | length 3
  Layer 1 - Top Layer w0.25: L5.2@76.1,16.55 C41.1@76.1,17.65 76.7,17.65 77.25,17.1 U6.10@77.75,17.1
NetC46_1: C46.1 U8.1 | length 3.7
  Layer 1 - Top Layer w0.25: U8.1@71.35,1.975 72.25,1.975 72.625,2.35 73.725,2.35 74.5,3.125 C46.1@74.5,3.15
NetC46_2: C46.2 U8.3 | length 2
  Layer 1 - Top Layer w0.25: U8.3@71.35,3.275 73.175,3.275 C46.2@73.3,3.15
NetC47_1: C47.1 U8.4 | length 3.4
  Layer 1 - Top Layer w0.25: U8.4@71.35,3.925 73.925,3.925 74.5,4.5 C47.1@74.5,4.55
NetC47_2: C47.2 U8.5 | length 2
  Layer 1 - Top Layer w0.25: U8.5@71.35,4.575 73.275,4.575 C47.2@73.3,4.55
NetC48_1: C48.1 U8.2 | length 4.9
  Layer 1 - Top Layer w0.25: U8.2@71.35,2.625 70.575,2.625 70.3,2.35 70.3,1.65 70.575,1.375 C48.1@73.25,1.375
NetC49_1: C49.1 U8.6 | length 2.3
  Layer 1 - Top Layer w0.25: U8.6@71.35,5.225 72.475,5.225 73.2,5.95 C49.1@73.3,5.95
NetC53_2: C53.2 J5.S1 J5.S2 R44.2 | length 64.3
  Layer 1 - Top Layer w0.8: R44.2@80.85,2.85 81.125,2.85 81.125,4.75 83.475,4.75 84.7,5.975 89.7,5.975 92.075,3.6 J5.S2@98.87,3.6
  Layer 1 - Top Layer w1.5: J5.S2@98.87,3.6 103.025,3.6 104.4,4.975 104.4,35.775 103.275,36.9 J5.S1@98.87,36.9
NetD1_1: D1.1 R4.1 | length 1.8
  Layer 1 - Top Layer w0.25: D1.1@7.38,9.775 R4.1@9.2,9.775
NetD2_1: D2.1 R5.2 | length 1.8
  Layer 1 - Top Layer w0.25: D2.1@7.38,13.775 R5.2@9.2,13.775
NetD5_1: D5.1 D11.1 F1.1 | length 7.1
  Layer 1 - Top Layer w0.508: D5.1@68.85,29.15 68.85,32.35 D11.1@69.5,32.35
  Layer 1 - Top Layer w0.6: D11.1@69.5,32.35 F1.1@72.7,32.35
NetD8_1: D8.1 R33.1 | length 1.8
  Layer 1 - Top Layer w0.25: D8.1@7.38,25.775 R33.1@9.2,25.775
NetD9_1: D9.1 R39.2 | length 1.8
  Layer 1 - Top Layer w0.25: D9.1@7.38,29.775 R39.2@9.2,29.775
NetD10_1: D10.1 R38.2 | length 1.8
  Layer 1 - Top Layer w0.25: D10.1@7.38,33.775 R38.2@9.2,33.775
NetD13_1: D13.1 R40.2 | length 2.4
  Layer 1 - Top Layer w0.25: D13.1@7.38,6.25 7.38,6.725 9.2,6.725 R40.2@9.2,6.85
NetFL1_1: FL1.1 R1.2 | length 3.6
  Layer 1 - Top Layer w0.762: R1.2@8.2,20.25 11.825,20.285
NetL7_1: L7.1 U5.1
NetR2_1: R2.1 U3.16 | length 13.8
  Layer 1 - Top Layer w0.15: U3.16@18.85,16.95 18.85,9.675 21.175,7.35 R2.1@24.4,7.35
NetR10_2: R10.2 U4.31 | length 4.4
  Layer 1 - Top Layer w0.15: U4.31@71.2,20.801 71.801,20.801 72,21 72,21.775 72.775,22.55 R10.2@74.4,22.55
NetR15_1: R15.1 R17.2 U5.7 | length 10.4
  Layer 1 - Top Layer w0.2: v1(50.85,22.5) 53.3,22.5 R15.1@53.3,22.25 ; v1(51.1,29.35) U5.7@51.1,30.05
  Layer 4 - Bottom Layer w0.25: v1(50.85,22.5) 51.1,22.75 v1(51.1,29.35)
NetR17_1: R17.1 R20.2 U5.9 | length 8.5
  Layer 1 - Top Layer w0.2: v1(52.1,29.35) U5.9@52.1,30.05
  Layer 1 - Top Layer w0.254: R20.2@50.4,23.55 50.55,23.7 v1(52.35,23.7)
  Layer 4 - Bottom Layer w0.254: v1(52.1,29.35) 52.1,23.95 v1(52.35,23.7)
NetR18_2: R18.2 R32.1 U5.8 | length 6.7
  Layer 1 - Top Layer w0.15: R18.2@50.4,24.95 R32.1@51.6,24.95 ; U5.8@51.6,30.05 R32.1@51.6,24.95 ; R32.1@52,24.95 51.7,24.95 R32.1@51.6,24.95
NetR34_1: R34.1 U9.8 | length 3.9
  Layer 1 - Top Layer w0.15: U9.8@79.025,11.425 78.475,11.425 78.475,11.95 78.65,12.125 80,12.125 80.875,11.25 R34.1@80.9,11.25
NetR35_1: R35.1 U9.7 | length 5.1
  Layer 1 - Top Layer w0.15: U9.7@79.025,10.775 78.525,10.775 78.1,11.2 78.1,12.075 78.5,12.475 80.525,12.475 R35.1@80.9,12.85
NetR36_1: R36.1 U9.5 | length 3.9
  Layer 1 - Top Layer w0.15: U9.5@79.025,9.475 78.475,9.475 78.475,8.95 78.65,8.775 80,8.775 80.875,9.65 R36.1@80.9,9.65
NetR37_1: R37.1 U9.6 | length 5.1
  Layer 1 - Top Layer w0.15: U9.6@79.025,10.125 78.525,10.125 78.1,9.7 78.1,8.825 78.5,8.425 80.525,8.425 R37.1@80.9,8.05
NRESET: C14.1 J3.10 R8.1 U3.19 | length 19
  Layer 1 - Top Layer w0.15: U3.19@19.5,18.6 20.15,18.6 v1(20.4,18.85) 21,18.85 C14.1@21.2,19.05 ; C14.1@20.925,19.125 R8.1@20.925,20.225
  Layer 4 - Bottom Layer w0.15: v1(20.4,18.85) 19.6,18.05 19.6,5.025 J3.10@20.94,3.685
P1.0: J1.5 U4.1 | length 49.3
  Layer 1 - Top Layer w0.15: v1(61.85,7.925) 61.375,8.4 61.375,10.925 63.05,12.6 U4.1@63.05,13.15
  Layer 4 - Bottom Layer w0.15: v1(61.85,7.925) 62.375,7.4 91.875,7.4 92.85,8.375 92.85,16.73 J1.5@90.6,18.98
P1.1: J1.4 U4.2 | length 44.9
  Layer 1 - Top Layer w0.15: v1(61.85,8.875) 61.85,10.85 63.55,12.55 U4.2@63.55,13.15
  Layer 4 - Bottom Layer w0.15: v1(61.85,8.875) 63,7.725 91.675,7.725 92.25,8.3 92.25,14.79 J1.4@90.6,16.44
P3.0: J11.2 R2.2 U4.19 | length 48.8
  Layer 1 - Top Layer w0.15: R2.2@25.6,7.35 38.55,7.35 42.56,11.36 J11.2@44.88,11.36 ; v1(70.45,14.799) U4.19@71.2,14.799
  Layer 4 - Bottom Layer w0.15: J11.2@44.88,11.36 62.085,11.36 65.2,14.475 68.625,14.475 68.8,14.3 69.951,14.3 v1(70.45,14.799)
P3.1: J11.3 U4.20 | length 27.8
  Layer 1 - Top Layer w0.15: J11.3@44.88,13.9 45.275,13.9 46.375,12.8 v1(58.675,12.8) ; v1(69.45,14.8) 69.949,15.299 U4.20@71.2,15.299
  Layer 4 - Bottom Layer w0.15: v1(58.675,12.8) 59.225,13.35 63.475,13.35 64.925,14.8 v1(69.45,14.8)
P4.7: J1.8 U4.38 | length 26.8
  Layer 1 - Top Layer w0.15: U4.38@68.05,21.95 68.05,24.1 v1(68.55,24.6)
  Layer 4 - Bottom Layer w0.15: v1(68.55,24.6) 69.7,25.75 71.125,25.75 72.4,24.475 87.2,24.475 89.325,26.6 J1.8@90.6,26.6
P6.6: J1.10 U4.49 | length 38.5
  Layer 1 - Top Layer w0.15: U4.49@62.4,21.301 62.899,21.301 v1(63.15,21.05)
  Layer 4 - Bottom Layer w0.15: v1(63.15,21.05) 63.95,21.85 67.225,21.85 69.5,24.125 71.901,24.125 72.151,23.875 88.55,23.875 89.875,25.2 91.4,25.2 92.15,25.95 92.15,30.13 J1.10@90.6,31.68
P6.7: J1.9 U4.50 | length 37.1
  Layer 1 - Top Layer w0.15: v1(61.65,21.35) 61.65,20.925 61.774,20.801 U4.50@62.4,20.801
  Layer 4 - Bottom Layer w0.15: v1(61.65,21.35) 62.575,22.275 67.075,22.275 69.375,24.575 71.876,24.575 72.276,24.175 87.95,24.175 89.275,25.5 91.075,25.5 91.7,26.125 91.7,28.04 J1.9@90.6,29.14
P7.0: J11.4 U4.57 | length 19.2
  Layer 1 - Top Layer w0.15: J11.4@44.88,16.44 45.245,16.075 45.525,16.075 45.75,15.85 46.475,15.85 47.5,14.825 59.425,14.825 61.9,17.3 U4.57@62.4,17.3
P7.1: J11.8 U4.58 | length 31.7
  Layer 1 - Top Layer w0.15: J11.8@44.88,26.6 43.45,25.17 43.45,16.175 44.15,15.475 46.25,15.475 47.35,14.375 59.45,14.375 61.875,16.8 U4.58@62.4,16.8
P7.2: J11.9 U4.59 | length 35.1
  Layer 1 - Top Layer w0.15: J11.9@44.88,29.14 43.05,27.31 43.05,16.013 43.888,15.175 45.95,15.175 47.175,13.95 59.5,13.95 61.85,16.3 U4.59@62.4,16.3
P7.3: J11.10 U4.60 | length 38.4
  Layer 1 - Top Layer w0.15: J11.10@44.88,31.68 42.675,29.475 42.675,15.75 43.575,14.85 45.675,14.85 47,13.525 59.6,13.525 61.875,15.8 U4.60@62.4,15.8
P8.0: J1.3 U4.17 | length 27.6
  Layer 1 - Top Layer w0.15: U4.17@71.2,13.799 71.626,13.799 71.7,13.725 71.7,8.6 v1(72.05,8.25)
  Layer 4 - Bottom Layer w0.15: v1(72.05,8.25) 72.675,8.875 86.55,8.875 90.6,12.925 J1.3@90.6,13.9
P8.1: J1.2 U4.18 | length 25.9
  Layer 1 - Top Layer w0.15: U4.18@71.2,14.299 71.626,14.299 72.075,13.85 72.075,9.225 v1(73.05,8.25)
  Layer 4 - Bottom Layer w0.15: v1(73.05,8.25) 87.49,8.25 J1.2@90.6,11.36
REFN0: C39.2 C40.2 R29.2 U6.6 | length 7.4
  Layer 1 - Top Layer w0.2: U6.6@79.65,18.5 79.65,19.4 81.55,21.3 84.35,21.3 84.35,20.35 R29.2@84.238,20.35
REFP0: C38.1 C39.1 R27.2 U6.7 | length 8.8
  Layer 1 - Top Layer w0.2: U6.7@79.15,18.5 79.15,19.9 81.85,22.6 84.35,22.6 84.35,23.55 R27.2@84.238,23.55 ; C38.1@84.35,22.45 C38.1@84.392,22.45
RF_N: FL1.3 U3.2 | length 1.7
  Layer 1 - Top Layer w0.15: FL1.3@13.079,20.453 13.277,20.65 14.65,20.65 U3.2@14.7,20.6
RF_P: FL1.4 U3.1 | length 1.7
  Layer 1 - Top Layer w0.15: FL1.4@13.079,21.278 13.307,21.05 14.65,21.05 U3.1@14.7,21.1
RS232_RXD: J5.25 U8.13 | length 43.2
  Layer 1 - Top Layer w0.2: U8.13@65.45,3.925 v1(66.65,3.925)
  Layer 4 - Bottom Layer w0.15: v1(66.65,3.925) 67.2,4.475 67.925,4.475 68.125,4.275 83.3,4.275 84.95,5.925 96.3,5.925 100.25,9.875 100.25,13.975 J5.25@101.41,15.135
RS232_TXD: J5.26 U8.14 | length 41.4
  Layer 1 - Top Layer w0.2: U8.14@65.45,3.275 66.95,3.275 v1(67.6,3.925)
  Layer 4 - Bottom Layer w0.15: v1(67.6,3.925) 83.575,3.925 85.275,5.625 96.675,5.625 101.41,10.36 J5.26@101.41,12.845
RS422_RX+: D7.2 J5.8 R34.2 R41.1 | length 18.1
  Layer 1 - Top Layer w0.2: R34.2@82.5,11.25 R41.1@84,11.25 85.925,11.25 87.45,12.775 89.275,12.775 89.6,12.45 92.325,12.45 93.45,13.575 95.025,13.575 95.2,13.4 95.2,13.15 95.025,12.975 94.425,12.975 94.275,12.825 94.275,12.525 94.425,12.375 95.55,12.375 96.02,12.845 J5.8@96.33,12.845
  Layer 1 - Top Layer w0.25: R34.2@82.5,11.25 R34.2@82.65,11.1
RS422_RX-: D7.1 J5.17 R35.2 R41.2 | length 17.2
  Layer 1 - Top Layer w0.2: R35.2@82.5,12.85 86.5,12.85 86.825,13.175 89.45,13.175 89.825,12.8 92.18,12.8 93.37,13.99 J5.17@98.87,13.99
RS422_TX+: D6.1 J5.18 R36.2 R42.1 | length 17.2
  Layer 1 - Top Layer w0.2: R36.2@82.5,9.65 86.875,9.65 87.507,10.282 91.907,10.282 93.325,11.7 J5.18@98.87,11.7
RS422_TX-: D6.2 J5.9 R37.2 R42.2 | length 18
  Layer 1 - Top Layer w0.2: R37.2@82.5,8.05 85.85,8.05 87.7,9.9 92.065,9.9 93.45,11.285 95.025,11.285 95.2,11.11 95.2,10.86 95.025,10.685 94.425,10.685 94.275,10.535 94.275,10.235 94.425,10.085 95.55,10.085 96.02,10.555 J5.9@96.33,10.555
